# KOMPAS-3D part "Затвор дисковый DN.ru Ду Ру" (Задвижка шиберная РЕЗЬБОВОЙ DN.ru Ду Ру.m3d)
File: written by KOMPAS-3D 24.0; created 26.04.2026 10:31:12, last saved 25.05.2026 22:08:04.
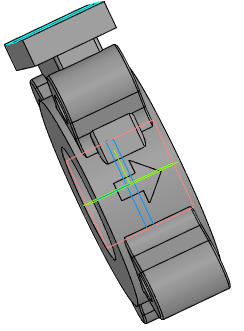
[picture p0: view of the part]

Document properties: Автор: R2D2; Полное имя файла: E:\Работа\Зайцев\GVKR1331M-1W-Fb-2P Задвижка шиберная с выдвижным штоком DN.ru Ду50-300 Ру16-10-6 с пневмоприводом\исходные материалы\DN65\Задвижка шиберная РЕЗЬБОВОЙ DN.ru Ду Ру.m3d

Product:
- Part/product: Затвор дисковый DN.ru Ду Ру
    Масса: 18.2
    Раздел спецификации: Прочие изделия
    Примечание: D050-23732

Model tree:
1. Смещенная плоскость:2
2. Диск
3. Корпус
4. Элемент выдавливания:3
     Расстояние 1 = 30
5. Элемент вращения:1
     Угол 1 = 360
6. Корпус штока
7. Элемент выдавливания:6  (with: Грань.Элемент вращения:1)
     Расстояние 1 = 92.5
8. Ушко  (with: Ребро.Элемент вращения:1)
9. Элемент выдавливания:5
10. Скругление:7  (with: Ребро.Элемент выдавливания:5)
     Радиус = 1
11. Эскиз:1  (with: Ребро.Элемент выдавливания:5)
12. Элемент выдавливания:12
     Расстояние 1 = 24; Расстояние 2 = 24
13. Элемент выдавливания:13
14. Массив по концентрической сетке:3  (with: Элемент выдавливания:5, Скругление:7, Элемент выдавливания:12, Элемент выдавливания:13)  (4 pattern instances)
     Шаг 2 = 360
15. Эскиз:2  (labels: Ребро.Элемент выдавливания:5.Экземпляр ( 1, 2 ); Ребро.Элемент выдавливания:5.Экземпляр ( 1, 3 ))
16. Элемент выдавливания:14
17. Эскиз:3  (with: Грань.Элемент выдавливания:6)
18. Элемент выдавливания:15
     Расстояние 2 = 15
19. Скругление:10  (with: Ребро.Элемент выдавливания:6)
     Радиус = 2
20. Эскиз:4  (labels: Задвижка шиберная с выдвижным штоком DN.ru Ду50 Ру16; Затвор дисковый DN.ru Ду200 Ру16)
21. Элемент выдавливания:16  (with: Грань.Элемент вращения:1)
     Расстояние 1 = 60; Смещение 1 = 1
22. Эскиз:5  (labels: Задвижка шиберная DN.ru Ду50 Ру10; Затвор дисковый DN.ru Ду200 Ру16)
23. Элемент выдавливания:17  (with: Грань.Элемент вращения:1)
     Расстояние 1 = 59.997; Смещение 1 = 1
24. Скругление:8  (with: Ребро.Элемент вращения:1)
     Радиус = 1
25. ЛЕЙБЛ
26. Элемент выдавливания:11  (with: Грань.Элемент выдавливания:6)
     Расстояние 1 = 13.5; Смещение 1 = 1

Expressions: 360/n; d/2+20; c-8-2*t; v1301/2; dd/2
Referenced files in E:\Работа\Зайцев\GVKR1331E-1W-Fb-2P Задвижка шиберная DN.ru Ду50-300 Ру16-10-6\исходные материалы\DN50\: GVKR1331E-1W-Fb-2P Задвижка шиберная с выдвижным штоком DN.ru Ду50 Ру16.a3d, GVKR1331E-1W-Fb-2P Задвижка шиберная DN.ru Ду50 Ру16.a3d
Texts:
  Угловой размер с обрывом
  GOST 26.020 Pr3
  var3D
  ширина затвора по металлу
  Диаметр исо фланца
  id4
  Диуметр отверстия  исо фланца
  id3
  ось отв. исо фланца
  DN+10
  dk-4
  Плоскость ZY.Начало координат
